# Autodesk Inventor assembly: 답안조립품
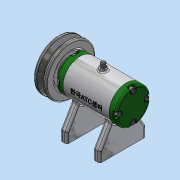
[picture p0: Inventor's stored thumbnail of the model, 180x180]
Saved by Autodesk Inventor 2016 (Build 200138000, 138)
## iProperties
Created: 2018-05
Part Number: 답안조립품
Material: 일반
Document SubType Name: Assembly
Designer: Administrator
Author: Administrator
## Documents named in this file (15)
- C:\Users\Administrator\Desktop\480507V1025\답안조립품.iam
- C:\Users\Administrator\Desktop\480507V1025\본체.ipt
- C:\Users\Administrator\Desktop\480507V1025\축.ipt
- C:\Users\Administrator\Desktop\480507V1025\베어링 6002.ipt
- C:\Users\Administrator\Desktop\480507V1025\뒤커버.ipt
- C:\Users\Administrator\Desktop\480507V1025\앞커버.ipt
- C:\Users\Administrator\Desktop\480507V1025\볼트 M4x12.ipt
- C:\Users\Administrator\Desktop\480507V1025\키 3x3x12.ipt
- C:\Users\Administrator\Desktop\480507V1025\V벨트풀리.ipt
- C:\Users\Administrator\Desktop\480507V1025\와셔 8x17.ipt
- C:\Users\Administrator\Desktop\480507V1025\스프링와셔 8.ipt
- C:\Users\Administrator\Desktop\480507V1025\너트 M8.ipt
- C:\Users\Administrator\Desktop\480507V1025\니플 M6x0.75.ipt
- C:\Users\Administrator\Desktop\480507V1025\와셔 6x11.5.ipt
- C:\Users\Administrator\Desktop\480507V1025\볼트 M6x8.ipt
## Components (1 placed, 1 different names)
1. V벨트풀리:1
